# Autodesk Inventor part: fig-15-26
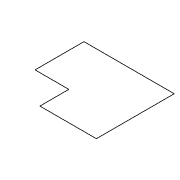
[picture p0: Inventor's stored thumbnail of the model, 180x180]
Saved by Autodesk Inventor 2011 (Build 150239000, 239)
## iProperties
Created: 2005-03
Part Number: fig-15-26
Document SubType Name: Sheet Metal
Designer: CADCIM
Manufacturer: Standard
Standards Organization: Custom
Density: 1 g/cm^3
Sheet Metal Rule: Default
Author: CADCIM
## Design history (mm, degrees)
sketch "Sketch1" dims "Thickness" = 0.5
  geometry: L1 (29.25, 32.25)-(-19.875, 32.25); L2 (-19.875, 32.25)-(-19.875, 5.625); L3 (-19.875, 5.625)-(-1.5, 5.625); L4 (-1.5, 5.625)-(-1.5, -10.125); L5 (-1.5, -10.125)-(29.25, -10.125); L6 (29.25, -10.125)-(29.25, 32.25)
  constraints: 12 end point, 4 parallel, 1 horizontal, 1 perpendicular
body "Solid1"
other parameters: "BendRadius" = 0.5 (= Thickness), "BendReliefWidth" = 0.5 (= Thickness), "BendReliefDepth" = 0.25 (= 0.5 x Thickness), "CornerReliefSize" = 2 (= 4 x Thickness), "SeamGap" = 0.01, "MinimumRemnant" = 1 (= 2 x Thickness), "TransitionRadius" = 0.5 (= BendRadius), "JacobiRadiusSize" = 0.5 (= Thickness), "GapSize" = 0.5 (= Thickness), "d0" = 0.5 (= BendRadius)
